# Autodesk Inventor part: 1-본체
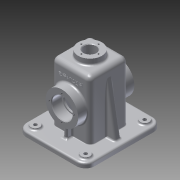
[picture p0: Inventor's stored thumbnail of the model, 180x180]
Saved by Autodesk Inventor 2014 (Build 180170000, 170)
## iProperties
Created: 2015-12
Part Number: 1-본체
Material: 알루미늄 6061
Document SubType Name: Modeling
Designer: Administrator
Density: 2.71 g/cm^3
Appearance: 알루미늄 - 평지
Mass: 806.058 g
Surface Area: 909.941 cm^2
Volume: 297.438 cm^3
Author: Administrator
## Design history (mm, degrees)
sketch "스케치1"
  geometry: L1 (-57.5, -65)-(57.5, -65); L2 (57.5, -65)-(57.5, 65); L3 (57.5, 65)-(-57.5, 65); L4 (-57.5, 65)-(-57.5, -65); L5 (-57.5, -65)-(57.5, 65); L6 (57.5, -65)-(-57.5, 65); L7 (-27.5, -27.5)-(27.5, -27.5); L8 (27.5, -27.5)-(27.5, 27.5); L9 (27.5, 27.5)-(-27.5, 27.5); L10 (-27.5, 27.5)-(-27.5, -27.5); L11 (-27.5, -27.5)-(27.5, 27.5); L12 (27.5, -27.5)-(-27.5, 27.5); 1 further point
  constraints: 24 end point, 4 midpoint, 4 parallel, 2 horizontal, 2 perpendicular
  dimensions: "d0" = 115 distance of L3.end L2.end; "d1" = 130 distance of L2.end L1.end; "d4" = 55 distance of L9.end L8.end; "d5" = 55 distance of L8.end L7.end
extrude "돌출1" new body sketch "스케치1" distance "d2" = 8; taper "d3" = 0 deg
sketch "스케치2"
  geometry: L1 (32.5, -32.5)-(-32.5, -32.5); L2 (-32.5, -32.5)-(-32.5, 32.5); L3 (-32.5, 32.5)-(32.5, 32.5); L4 (32.5, 32.5)-(32.5, -32.5); L5 (32.5, -32.5)-(-32.5, 32.5); L6 (-32.5, -32.5)-(32.5, 32.5); 1 further point
  constraints: 12 end point, 2 midpoint, 2 parallel, 1 horizontal, 1 perpendicular
  dimensions: "d6" = 65 distance of L2.end L3.end; "d7" = 65 distance of L1.end L2.end
extrude "돌출2" join sketch "스케치2" distance "d8" = 100; taper "d9" = 0 deg
sketch "스케치5"
  geometry: C1 r 10.5 at (0, 0); 1 further point
  constraints: 1 centre point, 1 coincident
  dimensions: "d13" = 21 diameter of C1
extrude "돌출4" cut sketch "스케치5" stored distance "d14" = 2; taper "d15" = 0 deg
sketch "스케치6"
  geometry: C1 r 10.5 at (0, 0) reference; C2 r 20 at (0, 0)
  constraints: 1 centre point, 1 coincident
  dimensions: "d16" = 40 diameter of C2
extrude "돌출5" join sketch "스케치6" distance "d17" = 10; taper "d18" = 0 deg
sketch "스케치7"
  geometry: L1 (-32.5, -32.5)-(32.5, -32.5) reference; L2 (-32.5, 32.5)-(-32.5, -32.5) reference; C1 r 20 at (0, 0) reference; A1 r 14.5 centre (0, 0) between (0, 14.5) and (14.5, 0); 2 further points
  constraints: 4 point on circle, 1 centre point, 1 coincident
  dimensions: "d19" = 29 diameter of A1; "d20" = 20.5061 distance of A1.end A1.start; "d21" = 20.5061 distance of A1.end point (0, -14.5); "d22" = 29 distance of A1.end point (-14.5, 0); "d23" = 47 distance from line of A1.end L2
hole "구멍1" sketch "스케치7" at (0, 14.5), (14.5, 0), (-14.5, 0), (0, -14.5) diameter "d24" = 2.459; stored, may be unused: countersink angle "d28" = 90 deg, drill point angle "d30" = 118 deg; dims "d25" = 7, "d26" = 4, "d27" = 2, "d29" = 9
sketch "스케치8"
  geometry: L1 (-32.5, -32.5)-(-32.5, 32.5) reference; L2 (-32.5, 32.5)-(32.5, 32.5) reference; L3 (32.5, 32.5)-(32.5, -32.5) reference; L4 (32.5, -32.5)-(-32.5, -32.5) reference; L5 (-57.5, -65)-(-57.5, 65) reference; L6 (-57.5, 65)-(57.5, 65) reference; L7 (57.5, 65)-(57.5, -65) reference; L8 (57.5, -65)-(-57.5, -65) reference; C1 r 3 at (-42.5, 50); C2 r 10.5 at (0, 0) reference; C3 r 3 at (-42.5, -50); C4 r 3 at (42.5, -50); C5 r 3 at (42.5, 50); 1 further point
  constraints: 4 centre point
  dimensions: "d31" = 6 diameter of C1; "d124" = 15 distance from line of L5 C1.centre; "d125" = 15 distance from line of L6 C1.centre; "d126" = 6 diameter of C3; "d127" = 6 diameter of C4; "d128" = 6 diameter of C5; "d129" = 100 distance of C3.centre C1.centre; "d130" = 85 distance of C3.centre C4.centre; "d131" = 100 distance of C5.centre C4.centre; "d132" = 15 distance from line of L7 C5.centre; "d133" = 15 distance from line of L6 C5.centre; "d134" = 15 distance from line of L7 C4.centre
  node "절단 모서리 투영7"
fillet "모깎기1" dims "d48" = 15
sketch "스케치10"
  geometry: L1 (0, 0)-(0, 100) reference; L2 (32.5, -8)-(32.5, 47); C1 r 27.5 at (32.5, 47)
  constraints: 2 end point, 1 centre point, 1 coincident, 1 parallel
  dimensions: "d50" = 55 distance of L2.start L2.end; "d51" = 55 diameter of C1
extrude "돌출8" join sketch "스케치10" distance "d52" = 15; taper "d53" = 0 deg
sketch "스케치11"
  geometry: L1 (-32.5, 53)-(32.5, 53) reference; L2 (20, 63)-(-20, 63) reference; C1 r 27.5 at (0, 0) reference; A1 r 21 centre (0, 0) between (0, 21) and (21, 0); 3 further points
  constraints: 4 point on circle, 1 centre point, 1 coincident
  dimensions: "d54" = 42 diameter of A1; "d55" = 63 distance from line of A1.end L2; "d56" = 42 distance from line of A1.start L2; "d57" = 84 distance from line of point (0, -21) L2; "d58" = 63 distance from line of point (-21, 0) L2
hole "구멍2" sketch "스케치11" at (0, 21), (21, 0), (0, -21), (-21, 0) diameter "d59" = 3.242; stored, may be unused: countersink angle "d63" = 90 deg, drill point angle "d65" = 118 deg; dims "d60" = 8, "d61" = 4, "d62" = 2, "d64" = 10
sketch "스케치12"
  geometry: C1 r 27.5 at (0, 0) reference; C2 r 17.5 at (0, 0); 1 further point
  constraints: 1 centre point, 1 coincident
  dimensions: "d66" = 35 diameter of C2
extrude "돌출9" cut sketch "스케치12" distance "d67" = 17; taper "d68" = 0 deg
sketch "스케치13"
  geometry: C1 r 17.5 at (0, 0) reference; C2 r 15 at (0, 0); 1 further point
  constraints: 1 centre point, 1 coincident
  dimensions: "d69" = 30 diameter of C2
extrude "돌출10" cut sketch "스케치13" distance "d70" = 3; taper "d71" = 0 deg
fillet "모깎기3" dims "d76" = 8
sketch "스케치25"
  geometry: L1 (10.5, 0)-(10.5, 118) reference; L2 (10.5, 118)-(13.271, 118) reference; L3 (13.271, 118)-(13.271, 109) reference; L4 (13.271, 109)-(14.5, 108.261) reference; L5 (14.5, 108.261)-(15.73, 109) reference; L6 (15.73, 109)-(15.73, 118) reference; L7 (15.73, 118)-(20, 118) reference; L8 (20, 118)-(20, 108) reference; L9 (20, 108)-(24.5, 108) reference; L10 (32.5, 100)-(32.5, 8) reference; L11 (32.5, 8)-(57.5, 8) reference; L12 (57.5, 8)-(57.5, 0) reference; L13 (57.5, 0)-(10.5, 0) reference; L14 (-10.5, 118)-(-10.5, 0) reference; L15 (-10.5, 0)-(-57.5, 0) reference; L16 (-57.5, 8)-(-32.5, 8) reference; L17 (-32.5, 8)-(-32.5, 100) reference; L18 (-24.5, 108)-(-20, 108) reference; L19 (-20, 108)-(-20, 118) reference; L20 (-20, 118)-(-15.73, 118) reference; L21 (-15.73, 118)-(-15.73, 109) reference; L22 (-15.73, 109)-(-14.5, 108.261) reference; L23 (-14.5, 108.261)-(-13.271, 109) reference; L24 (-13.271, 109)-(-13.271, 118) reference; L25 (-13.271, 118)-(-10.5, 118) reference; L26 (57.5, 8)-(47.5, 8); L27 (47.5, 8)-(30.6, 103.845); L28 (-57.5, 0)-(-57.5, 8) reference; A1 r 8 centre (24.5, 100) between (32.5, 100) and (24.5, 108) reference; A2 r 8 centre (-24.5, 100) between (-24.5, 108) and (-32.5, 100) reference; 1 further point
  constraints: 4 end point, 1 point on line
  dimensions: "d92" = 10 distance of L11.end L26.end; "d93" = 10 deg angle of L12 L27
  node "절단 모서리 투영3"
fillet "모깎기5" dims "d94" = 0.3
sketch "스케치29"
  geometry: L1 (57.5, 8)-(57.5, 0) reference; L2 (57.5, 8)-(47.5, 8); L3 (-57.5, 0)-(-57.5, 8) reference; L4 (10.5, 0)-(10.5, 118) reference; L5 (10.5, 118)-(13.271, 118) reference; L6 (13.271, 118)-(13.271, 109) reference; L7 (13.271, 109)-(14.5, 108.261) reference; L8 (14.5, 108.261)-(15.73, 109) reference; L9 (15.73, 109)-(15.73, 118) reference; L10 (15.73, 118)-(20, 118) reference; L11 (20, 118)-(20, 108) reference; L12 (20, 108)-(24.5, 108) reference; L13 (32.5, 100)-(32.5, 8) reference; L14 (32.5, 8)-(57.5, 8) reference; L15 (57.5, 8)-(57.5, 0) reference; L16 (57.5, 0)-(10.5, 0) reference; L17 (-10.5, 118)-(-10.5, 0) reference; L18 (-10.5, 0)-(-57.5, 0) reference; L19 (-57.5, 0)-(-57.5, 8) reference; L20 (-57.5, 8)-(-32.5, 8) reference; L21 (-32.5, 8)-(-32.5, 100) reference; L22 (-24.5, 108)-(-20, 108) reference; L23 (-20, 108)-(-20, 118) reference; L24 (-20, 118)-(-15.73, 118) reference; L25 (-15.73, 118)-(-15.73, 109) reference; L26 (-15.73, 109)-(-14.5, 108.261) reference; L27 (-14.5, 108.261)-(-13.271, 109) reference; L28 (-13.271, 109)-(-13.271, 118) reference; L29 (-13.271, 118)-(-10.5, 118) reference; L30 (47.5, 8)-(32.5, 93.069); A1 r 8 centre (24.5, 100) between (32.5, 100) and (24.5, 108) reference; A2 r 8 centre (-24.5, 100) between (-24.5, 108) and (-32.5, 100) reference; 1 further point
  constraints: 4 end point, 1 perpendicular, 1 point on line
  dimensions: "d119" = 10 distance of L1.start L2.end; "d121" = 10 deg angle of L15 L30
extrude "돌출17" join sketch "스케치29" stored distance "d122" = 10; taper "d123" = 0 deg
extrude "돌출18" cut sketch "스케치8" distance "d135" = 10; taper "d136" = 0 deg
sketch "스케치31"
  geometry: C1 r 3 at (42.5, -50) reference; C2 r 3 at (-42.5, 50) reference; C3 r 3 at (-42.5, -50) reference; C4 r 3 at (42.5, 50) reference; C5 r 7.5 at (42.5, 50); C6 r 7.5 at (42.5, -50); C7 r 7.5 at (-42.5, -50); C8 r 7.5 at (-42.5, 50); A1 r 15 centre (42.5, 50) between (57.5, 50) and (42.5, 65) reference; A2 r 15 centre (-42.5, 50) between (-42.5, 65) and (-57.5, 50) reference; A3 r 15 centre (-42.5, -50) between (-57.5, -50) and (-42.5, -65) reference; A4 r 15 centre (42.5, -50) between (42.5, -65) and (57.5, -50) reference; 1 further point
  constraints: 4 centre point, 4 coincident
  dimensions: "d137" = 15 diameter of C5; "d138" = 15 diameter of C6; "d139" = 15 diameter of C7; "d140" = 15 diameter of C8
extrude "돌출19" join sketch "스케치31" distance "d141" = 3; taper "d142" = 0 deg
fillet "모깎기6" dims "d143" = 3
fillet "모깎기7" dims "d144" = 8
fillet "모깎기8" dims "d145" = 3
fillet "모깎기9" dims "d146" = 3
chamfer "모따기1" distance "d147" = 1; stored, may be unused: second distance "d148" = 2, angle "d149" = 45 deg
chamfer "모따기2" distance "d152" = 1; stored, may be unused: second distance "d153" = 2, angle "d154" = 45 deg
sketch "스케치32"
  geometry: L1 (-8, 0)-(-8, -92) reference; L2 (49, 8)-(0, 8) reference; L3 (44.5, 18)-(4.5, 18) reference; 3 further points
  constraints: 1 other
  dimensions: "d186" = 28 distance from line of point (24.5, -10) L3; "d187" = 32.5 distance from line of point (24.5, -10) L1
sketch "스케치34"
  geometry: L1 (42.5, -60)-(-42.5, -60); L2 (-52.5, -50)-(-52.5, 50); L3 (-42.5, 60)-(42.5, 60); L4 (52.5, 50)-(52.5, -50); L5 (52.5, -60)-(-52.5, 60); L6 (-52.5, -60)-(52.5, 60); C1 r 3 at (-42.5, -50) reference; C2 r 3 at (42.5, 50) reference; C3 r 3 at (42.5, -50) reference; C4 r 3 at (-42.5, 50) reference; C5 r 10.5 at (0, 0) reference; A1 r 10 centre (-42.5, 50) between (-42.5, 60) and (-52.5, 50); A2 r 10 centre (42.5, 50) between (52.5, 50) and (42.5, 60); A3 r 10 centre (42.5, -50) between (42.5, -60) and (52.5, -50); A4 r 10 centre (-42.5, -50) between (-52.5, -50) and (-42.5, -60)
  constraints: 12 end point, 8 point on circle, 8 point on line, 8 tangent, 4 centre point, 3 equal radius, 2 midpoint, 2 parallel, 1 horizontal, 1 perpendicular
  dimensions: "d170" = 105 distance of L5.end L6.end; "d171" = 120 distance of L6.start L5.end; "d172" = 10 radius of A1
extrude "돌출21" join sketch "스케치34" distance "d173" = 2; taper "d174" = 0 deg
sketch "스케치35"
  geometry: L1 (27.5, -27.5)-(-27.5, -27.5); L2 (-27.5, -27.5)-(-27.5, 27.5); L3 (-27.5, 27.5)-(27.5, 27.5); L4 (27.5, 27.5)-(27.5, -27.5); L5 (27.5, -27.5)-(-27.5, 27.5); L6 (-27.5, -27.5)-(27.5, 27.5); C1 r 10.5 at (0, 0) reference
  constraints: 12 end point, 2 midpoint, 2 parallel, 1 horizontal, 1 perpendicular
  dimensions: "d175" = 55 distance of L2.end L3.end; "d176" = 55 distance of L1.end L2.end
extrude "돌출22" cut sketch "스케치35" distance "d177" = 105; taper "d178" = 0 deg
fillet "모깎기18" dims "d179" = 3
fillet "모깎기19" dims "d180" = 3
sketch "스케치36"
  geometry: L1 (27.5, -2)-(27.5, 100) reference; L2 (65, 5)-(65, 0) reference; L3 (-50, 8)-(50, 8) reference; L4 (27.5, 8)-(42.5, 8); L5 (42.5, 8)-(42.5, 31.676); L6 (42.5, 31.676)-(27.5, 31.676); 1 further point
  constraints: 6 end point, 4 point on line, 2 perpendicular
  dimensions: "d181" = 15 distance of L4.start L4.end; "d182" = 23.6761 distance between parallel lines of L3 L6
extrude "돌출23" join sketch "스케치36" stored distance "d183" = 6; taper "d184" = 0 deg
fillet "모깎기20" dims "d185" = 3
feature "엠보싱2" dims "d8" = 100, "d188" = 0.5, "d189" = 0
fillet "모깎기21" dims "d190" = 1
fillet "모깎기22" dims "d191" = 1
fillet "모깎기23" dims "d192" = 3
fillet "모깎기24" dims "d193" = 3
node "솔리드1"
mirror "대칭1"
mirror "대칭2"
mirror "대칭3"
mirror "대칭4"
node "작업 평면1"
node "절단 모서리 투영6"
other parameters: "d120" = 10 deg
